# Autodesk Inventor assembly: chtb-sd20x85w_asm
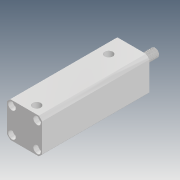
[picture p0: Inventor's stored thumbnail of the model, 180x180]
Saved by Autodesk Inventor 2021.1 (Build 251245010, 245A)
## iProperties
Company: Microsoft
Created: 2018-05
Part Number: chtb-sd20x85w_asm
Description: STEP AP214
Document SubType Name: Assembly
Designer: user
Title: chtb-sd20x85w_asm.STEP
Author: Windows
Revision Number: ÈÎºÎ
Sending System: SolidWorks 2015
Preprocessor: SwSTEP 2.0
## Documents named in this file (4)
- D:\Vault_2016\Projekty\Clamptek\Hydraulic\CHTB\CHTB-20\Inventor\CHTB-SD20x85W\chtb-sd20x85w_asm.iam
- D:\Vault_2016\Projekty\Clamptek\Hydraulic\CHTB\CHTB-20\Inventor\CHTB-SD20x85W\CHTB-SD20X85NBT.ipt
- D:\Vault_2016\Projekty\Clamptek\Hydraulic\CHTB\CHTB-20\Inventor\CHTB-SD20x85W\CHTB-SD20X85WHSG.ipt
- D:\Vault_2016\Projekty\Clamptek\Hydraulic\CHTB\CHTB-20\Inventor\CHTB-SD20x85W\QG.ipt
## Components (3 placed, 3 different names)
1. CHTB-SD20X85NBT_1
2. CHTB-SD20X85WHSG_2
3. QG_3
